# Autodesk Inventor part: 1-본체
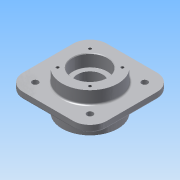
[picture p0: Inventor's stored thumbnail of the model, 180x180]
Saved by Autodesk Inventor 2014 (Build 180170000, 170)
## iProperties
Created: 2015-09
Part Number: 1-본체
Material: 알루미늄 6061
Document SubType Name: Modeling
Designer: study
Density: 2.71 g/cm^3
Appearance: 알루미늄 - 평지
Author: study
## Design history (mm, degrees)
sketch "스케치1"
  geometry: L1 (-75, 75)-(75, 75); L2 (75, 75)-(75, -75); L3 (75, -75)-(-75, -75); L4 (-75, -75)-(-75, 75); L5 (-75, 75)-(75, -75); L6 (75, 75)-(-75, -75); 1 further point
  constraints: 12 end point, 2 midpoint, 2 parallel, 1 horizontal, 1 perpendicular
  dimensions: "d0" = 150 distance of L1.start L1.end; "d1" = 150 distance of L1.end L2.end
extrude "돌출1" new body sketch "스케치1" stored distance "d2" = 12; taper "d3" = 0 deg
node "작업 평면1"
sketch "스케치2"
  geometry: C1 r 50 at (0, 0); 1 further point
  constraints: 1 centre point, 1 coincident
  dimensions: "d5" = 100 diameter of C1
extrude "돌출2" join sketch "스케치2" distance "d6" = 70; taper "d7" = 0 deg
sketch "스케치3"
  geometry: L1 (75, 75)-(-75, 75) reference; L2 (-75, 75)-(-75, -75) reference; L3 (-75, -75)-(75, -75) reference; L4 (75, -75)-(75, 75) reference; L5 (-49, 49)-(49, 49); L6 (49, 49)-(49, -49); L7 (49, -49)-(-49, -49); L8 (-49, -49)-(-49, 49); C1 r 10 at (-49, 49); C2 r 10 at (49, 49); C3 r 10 at (49, -49); C4 r 10 at (-49, -49)
  constraints: 8 end point, 4 centre point, 4 coincident, 3 equal radius, 3 other
  dimensions: "d8" = 98 distance of L5.end L6.end; "d9" = 20 diameter of C1
extrude "돌출3" join sketch "스케치3" distance "d10" = 5; taper "d11" = 0 deg
sketch "스케치4"
  geometry: C1 r 10 at (0, 0) reference; C2 r 10 at (98, 0) reference; C3 r 10 at (98, -98) reference; C4 r 10 at (0, -98) reference; 5 further points
  constraints: 4 coincident
hole "구멍1" sketch "스케치4" at (0, 0), (98, 0), (98, -98), (0, -98) diameter "d12" = 11; stored, may be unused: countersink angle "d16" = 90 deg, drill point angle "d18" = 118 deg; dims "d13" = 6, "d14" = 4, "d15" = 2, "d17" = 8
sketch "스케치5"
  geometry: L1 (28.991, -28.991)-(-28.991, -28.991); L2 (-28.991, -28.991)-(-28.991, 28.991); L3 (-28.991, 28.991)-(28.991, 28.991); L4 (28.991, 28.991)-(28.991, -28.991); C1 r 50 at (0, 0) reference; A1 r 41 centre (0, 0) between (28.991, -28.991) and (28.991, 28.991); 4 further points
  constraints: 8 end point, 4 coincident, 2 point on circle, 1 centre point, 1 point on line, 1 vertical, 9 other
  dimensions: "d19" = 82 diameter of A1
hole "구멍2" sketch "스케치5" at (-28.991, 28.991), (-28.991, -28.991), (28.991, -28.991), (28.991, 28.991) diameter "d20" = 4.917; stored, may be unused: countersink angle "d24" = 90 deg, drill point angle "d26" = 118 deg; dims "d21" = 10, "d22" = 4, "d23" = 2, "d25" = 13
hole "구멍3" diameter "d29" = 45; stored, may be unused: countersink angle "d33" = 90 deg, drill point angle "d35" = 118 deg; dims "d27" = 10, "d28" = 10, "d30" = 10, "d31" = 62, "d32" = 22, "d34" = 13
node "작업 평면2"
sketch "스케치6"
  geometry: C1 r 50 at (0, 0) reference; 1 further point
  constraints: 1 vertical alignment, 1 other
  dimensions: "d36" = 65 distance of C1.centre point (0, 65)
feature "엠보싱1" sketch "스케치6" dims "d0" = 150, "d1" = 150, "d37" = 1, "d38" = 0
fillet "모깎기1" dims "d39" = 30
fillet "모깎기2" dims "d40" = 3, "d41" = 0.3
chamfer "모따기1" distance "d42" = 1; stored, may be unused: second distance "d43" = 2, angle "d44" = 45 deg
node "솔리드1"
mirror "대칭1"
node "투영된 루프1"
node "투영된 루프2"
node "투영된 루프3"
other parameters: "d4" = 23
